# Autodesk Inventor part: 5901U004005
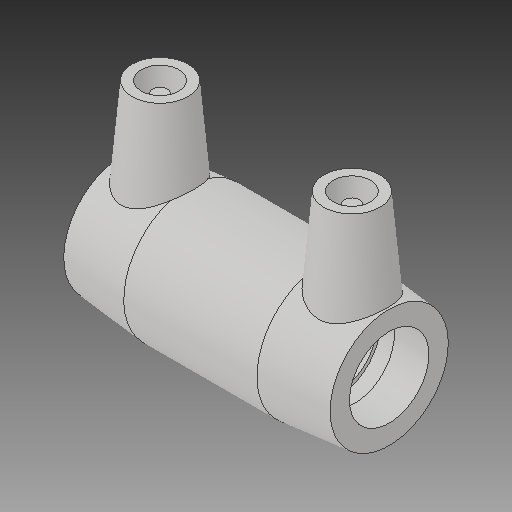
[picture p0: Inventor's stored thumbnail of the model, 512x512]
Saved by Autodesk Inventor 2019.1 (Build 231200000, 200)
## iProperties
Created: 2017-06
Part Number: 5901U004005
Material: Generic
Description: PLASSON CTS COUPLER 1/2''
Document SubType Name: Modeling
Designer: KIM
Mass: 72.9589 g
Surface Area: 285.531 cm^2
Volume: 72.9589 cm^3
Density: 1 g/cm^3
Appearance: Default
Author: KIM
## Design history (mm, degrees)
derived "5901U.ipt"
feature "Solid1::5901U.ipt"
tag "TaggingFeature1"
body "Solid1"
other parameters: "d0" = 71.12, "d1" = 21.2, "d2" = 35.052, "d3" = 34.544, "d4" = 17.78, "d5" = 31.5468, "d6" = 16.96, "d7" = 21.2, "d8" = 168 deg, "d10" = 13.8176, "d11" = 4.60587, "d29" = 38.1, "d30" = 15, "d31" = 25.6032, "d34" = 5 deg, "d41" = 4, "d42" = 14, "d43" = 0, "d48" = 3, "d49" = 0, "d_" = 21.2, "L_" = 71.12, "L_1" = 34.544, "D_" = 35.052, "A_" = 38.1, "d_2" = 12
